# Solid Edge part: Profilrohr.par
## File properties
Username: ahadarics
Dokumentum tartalom típus: 0
Author: ahadarics
Last saved by: ahadarics
Revision: 84
Sűrűség: 0,000 kg/m^3
Pontosság: 0,990
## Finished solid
Body 1: solid body, 6 faces, 6 edges, 0 vertices.
  Faces by surface: cone 2, cylinder 2, plane 2
  Edges by curve: circle 6
Bounding box of the edges (mm): 21.270 x 21.270 x 282.000, from (-10.635, -10.635, -261) to (10.635, 10.635, 21).
Cylindrical faces by radius (mm): R10 x1, R10.635 x1
Conical faces (half-angle, radius in mm at the cone's reference point): 15 deg R10.067 x2
Planar faces by outward normal: +z 1, -z 1
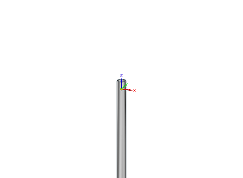
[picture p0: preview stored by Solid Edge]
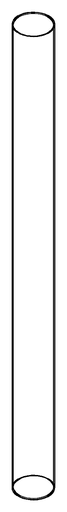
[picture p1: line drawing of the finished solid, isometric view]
